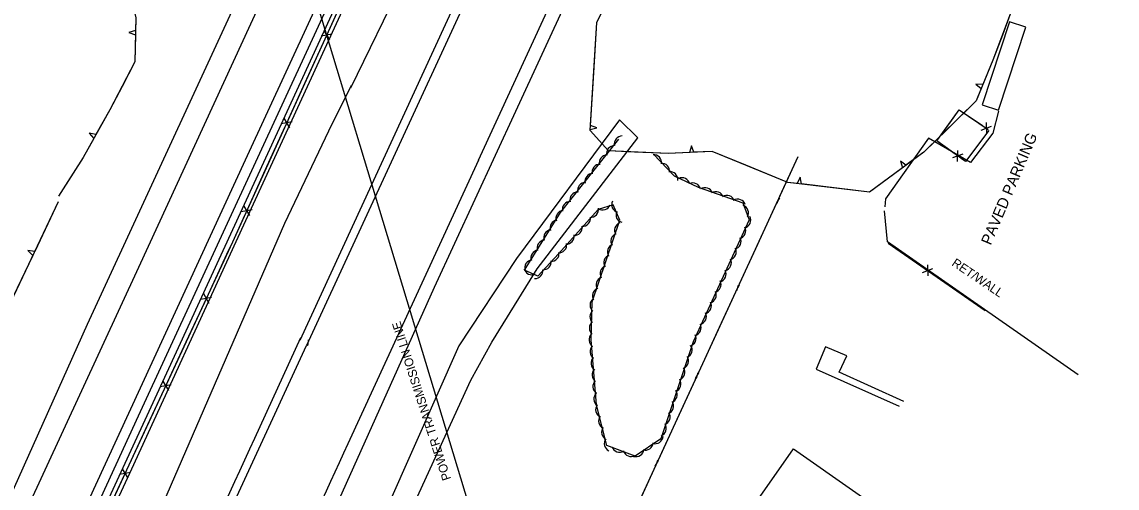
# Model space of a CAD drawing. Extents: x 978516 to 993312, y 1836504 to 1846212.
# Drawn here: x 982303.7 to 982802.5, y 1844142.7 to 1844355.2 of the extents above; entities that cross this region are included whole.
import ezdxf

# ---------------------------------------------------------------- set-up
doc = ezdxf.new("R2010")
doc.units = 0
for name, color, linetype in [('S_BUILDING', 7, 'Continuous'), ('S_EDGE_PAVEMENT', 7, 'Continuous'), ('S_FENCE', 7, 'Continuous'), ('S_IRON_PIN_ANNOT', 7, 'Continuous'), ('S_LANDSCAPING', 7, 'Continuous'), ('S_MISC_STRUCTURES', 7, 'Continuous'), ('S_PARKING', 7, 'Continuous'), ('S_PARKING_ANNOT', 7, 'Continuous'), ('S_SHOULDER', 7, 'Continuous'), ('S_SIDE_DRAIN', 7, 'Continuous'), ('S_SIDEWALK', 7, 'Continuous'), ('S_STREAM', 7, 'Continuous'), ('S_TREE', 7, 'Continuous'), ('S_UTILITY_POLE', 7, 'Continuous'), ('S_UTILITY_POLE_ANNOT', 7, 'Continuous')]:
    doc.layers.add(name, color=color, linetype=linetype)

msp = doc.modelspace()

# ---------------------------------------------------------------- linework, layer by layer
at = {"layer": 'S_BUILDING'}
msp.add_lwpolyline([(982748.58, 1844314.99), (982761, 1844352.77), (982753.47, 1844355.24), (982741.06, 1844317.46)], close=True, dxfattribs=at)
at = {"layer": 'S_EDGE_PAVEMENT'}
for points in [[(982779.67, 1844959.64), (982752.16, 1844900.15), (982714.25, 1844817.37), (982639.59, 1844655.47), (982545.18, 1844450.47), (982433.25, 1844207.72)], [(982511.65, 1844292.15), (982660.01, 1844614.55), (982735.58, 1844778.86), (982764.16, 1844843.59), (982802.52, 1844939.43)], [(982273.73, 1844064.89), (982288.19, 1844094.69), (982356.96, 1844243.34), (982421.2, 1844383.21)], [(982444.31, 1844376.55), (982405.39, 1844292.19), (982337.22, 1844143.95), (982258.29, 1843972.49), (982199.49, 1843845.15), (982150.27, 1843738.07), (982091.93, 1843611.5), (982046.43, 1843512.73)], [(982511.65, 1844292.15), (982452.19, 1844162.82)], [(982434.11, 1844208.11), (982434.24, 1844210.25)], [(982101.67, 1843487.19), (982177.28, 1843651.48), (982263.35, 1843838.34), (982337.41, 1843999.45), (982433.25, 1844207.72), (982434.11, 1844208.11)]]:
    msp.add_lwpolyline(points, dxfattribs=at)
msp.add_ellipse((985046.29, 1843010.45), major_axis=(-1542.42, -2755.9), ratio=0.898055, start_param=4.795233, end_param=4.843255, dxfattribs=at)
at = {"layer": 'S_FENCE'}
for p, q in [((982444.93, 1844349.65), (982440.03, 1844348.74)), ((982441.21, 1844351.35), (982443.75, 1844347.04)), ((982426.72, 1844309.61), (982421.82, 1844308.7)), ((982423.01, 1844311.31), (982425.54, 1844307)), ((982742.92, 1844309.32), (982742.99, 1844304.32)), ((982740.62, 1844305.93), (982745.29, 1844307.71)), ((982732.32, 1844294.9), (982727.59, 1844293.3)), ((982729.9, 1844291.6), (982730.01, 1844296.6)), ((982648.71, 1844275.09), (982647.19, 1844272.44)), ((982648.39, 1844275.04), (982647.51, 1844272.48)), ((982408.51, 1844269.57), (982403.61, 1844268.66)), ((982404.8, 1844271.27), (982407.33, 1844266.96)), ((982716.24, 1844244.4), (982716.27, 1844239.4)), ((982713.91, 1844241.03), (982718.6, 1844242.76)), ((982630.32, 1844235.15), (982628.8, 1844232.5)), ((982630, 1844235.1), (982629.12, 1844232.55)), ((982390.12, 1844229.6), (982385.21, 1844228.73)), ((982386.41, 1844231.33), (982388.91, 1844227)), ((982611.93, 1844195.22), (982610.42, 1844192.57)), ((982611.61, 1844195.17), (982610.74, 1844192.61)), ((982371.61, 1844189.7), (982366.7, 1844188.83)), ((982367.91, 1844191.43), (982370.4, 1844187.1)), ((982593.55, 1844155.28), (982592.03, 1844152.63)), ((982593.23, 1844155.24), (982592.35, 1844152.68)), ((982353.11, 1844149.8), (982348.19, 1844148.92)), ((982349.4, 1844151.52), (982351.9, 1844147.2))]:
    msp.add_line(p, q, dxfattribs=at)
for points in [[(982451.59, 1844369.22), (982399.56, 1844254.82), (982308.24, 1844057.91)], [(982451.59, 1844369.22), (982443.31, 1844351.02)], [(982441.65, 1844347.38), (982433.38, 1844329.18)], [(982433.38, 1844329.18), (982425.1, 1844310.98)], [(982744.06, 1844305.71), (982733.42, 1844291.56), (982720.48, 1844301.06), (982730.66, 1844315.16), (982743.86, 1844306.2)], [(982726.48, 1844309.36), (982730.66, 1844315.16), (982741.3, 1844307.94)], [(982728.34, 1844295.29), (982720.48, 1844301.06), (982726.48, 1844309.36)], [(982423.44, 1844307.34), (982415.17, 1844289.14)], [(982744.06, 1844305.71), (982733.42, 1844291.56), (982731.57, 1844292.92)], [(982415.17, 1844289.14), (982406.89, 1844270.94)], [(982657.14, 1844293.73), (982591.49, 1844151.14), (982536.58, 1844030.85)], [(982657.14, 1844293.73), (982648.78, 1844275.58)], [(982647.11, 1844271.95), (982638.75, 1844253.79)], [(982405.23, 1844267.3), (982399.56, 1844254.82), (982396.91, 1844249.12)], [(982698.19, 1844254.4), (982714.61, 1844243.03)], [(982698.19, 1844254.4), (982742.51, 1844223.71)], [(982396.91, 1844249.12), (982388.5, 1844230.98)], [(982638.75, 1844253.79), (982630.4, 1844235.64)], [(982717.9, 1844240.76), (982734.31, 1844229.39)], [(982628.73, 1844232.01), (982620.37, 1844213.86)], [(982734.31, 1844229.39), (982742.51, 1844223.71)], [(982386.82, 1844227.35), (982378.41, 1844209.21)], [(982378.41, 1844209.21), (982370, 1844191.08)], [(982620.37, 1844213.86), (982612.01, 1844195.71)], [(982610.34, 1844192.08), (982601.98, 1844173.93)], [(982368.31, 1844187.45), (982359.9, 1844169.31)], [(982359.9, 1844169.31), (982351.49, 1844151.17)], [(982601.98, 1844173.93), (982593.62, 1844155.77)], [(982591.95, 1844152.14), (982591.49, 1844151.14), (982583.68, 1844134.02)], [(982349.81, 1844147.55), (982341.4, 1844129.41)]]:
    msp.add_lwpolyline(points, dxfattribs=at)
at = {"layer": 'S_IRON_PIN_ANNOT'}
msp.add_lwpolyline([(982784.77, 1844194.32), (982697.96, 1844254.98), (982696.63, 1844269.13)], dxfattribs=at)
at = {"layer": 'S_MISC_STRUCTURES'}
msp.add_lwpolyline([(982459.15, 1844381.2), (982401.18, 1844255.02), (982353.6, 1844151.37), (982293.53, 1844021.64), (982233.45, 1843890.75), (982165.83, 1843744.12), (982112.95, 1843629.64), (982097.77, 1843596.62), (982091.45, 1843577), (982071.61, 1843534.32), (982068.38, 1843535.71), (982088.3, 1843578.12), (982096.35, 1843601.36), (982110.1, 1843631.18), (982228.09, 1843887.64), (982301.61, 1844047.37), (982364.37, 1844183.75), (982455.44, 1844381.81), (982456.19, 1844383.33)], dxfattribs=at)
at = {"layer": 'S_PARKING'}
for points in [[(982748.55, 1844314.55), (982745.93, 1844304.53), (982735.73, 1844291.12), (982716.57, 1844302.26), (982697.03, 1844274.58), (982696.68, 1844270.86)], [(982717.91, 1844043.16), (982620.49, 1844110.96), (982655.12, 1844160.56), (982713.37, 1844119.72)]]:
    msp.add_lwpolyline(points, dxfattribs=at)
at = {"layer": 'S_SHOULDER'}
for points in [[(982430.43, 1844210.12), (982524.82, 1844415.67), (982632.61, 1844650.66), (982722.13, 1844843.9), (982785.87, 1844983.8)], [(982805.21, 1844925.87), (982773.09, 1844849.82), (982754.04, 1844807.09), (982715.23, 1844720.47), (982650.33, 1844578.31), (982528.53, 1844314.43)], [(982281.93, 1844102.29), (982333.5, 1844217.4), (982416.97, 1844398.31)], [(982448.76, 1844375.28), (982356.61, 1844175.48), (982282.66, 1844014.59), (982233, 1843906.78), (982168.28, 1843765.4), (982106.74, 1843632.71), (982066.39, 1843545.71)], [(982528.53, 1844314.43), (982491.54, 1844234.12), (982441.42, 1844122.41), (982416.93, 1844065.19), (982403.54, 1844032.8)], [(982409.72, 1844165.47), (982430.67, 1844211.3), (982430.67, 1844211.3)]]:
    msp.add_lwpolyline(points, dxfattribs=at)
msp.add_ellipse((981492.34, 1844624.74), major_axis=(2158.84, 4724.25), ratio=0.197395, start_param=4.671769, end_param=4.705376, dxfattribs=at)
at = {"layer": 'S_SIDE_DRAIN'}
msp.add_lwpolyline([(982477.92, 1844125.85), (982508.24, 1844191.94), (982517.73, 1844209.18), (982538.43, 1844242.71), (982584.17, 1844302.32), (982575.94, 1844310.66), (982529, 1844247.39), (982502.74, 1844207.51), (982471.02, 1844135.94)], dxfattribs=at)
at = {"layer": 'S_SIDEWALK'}
msp.add_lwpolyline([(982705.47, 1844182.18), (982675.93, 1844195.5), (982679.5, 1844203.01), (982669.7, 1844207.13), (982665.52, 1844196.93), (982703.34, 1844180.05)], dxfattribs=at)
at = {"layer": 'S_STREAM'}
for points in [[(982514.14, 1844454.86), (982497.09, 1844420.18), (982477.21, 1844374.11), (982453.29, 1844325.07)], [(982296.86, 1843981.53), (982335.53, 1844064.99), (982369.8, 1844139.96), (982423.52, 1844263.5), (982443.56, 1844305.64), (982453.87, 1844326.44)]]:
    msp.add_lwpolyline(points, dxfattribs=at)
at = {"layer": 'S_TREE'}
for p, q in [((982355.46, 1844351.33), (982352.46, 1844350.46)), ((982352.46, 1844350.46), (982355.42, 1844349.37)), ((982741.38, 1844326.63), (982738.26, 1844326.91)), ((982738.26, 1844326.91), (982740.66, 1844324.87)), ((982337.39, 1844303.85), (982334.32, 1844304.5)), ((982334.32, 1844304.5), (982336.43, 1844302.14)), ((982562.51, 1844306.18), (982565.55, 1844306.88)), ((982565.55, 1844306.88), (982562.63, 1844308.06)), ((982608.61, 1844298.75), (982607.75, 1844295.72)), ((982609.71, 1844295.81), (982608.61, 1844298.75)), ((982706.35, 1844289.86), (982703.82, 1844291.72)), ((982703.82, 1844291.72), (982704.76, 1844288.7)), ((982658.24, 1844284.41), (982656.85, 1844281.57)), ((982658.79, 1844281.33), (982658.24, 1844284.41)), ((982309.53, 1844250.56), (982306.42, 1844250.99)), ((982306.42, 1844250.99), (982308.69, 1844248.78))]:
    msp.add_line(p, q, dxfattribs=at)
for points in [[(982804.27, 1844516.15), (982793.6, 1844477.25), (982784.63, 1844454.32), (982771.91, 1844403.14), (982762.4, 1844378), (982753.89, 1844358.77), (982745.95, 1844337.86), (982738.36, 1844319.23), (982714.53, 1844295.87), (982689.69, 1844277.63), (982652.61, 1844282.07), (982618.06, 1844296.21), (982598.05, 1844295.25), (982570.83, 1844296.38), (982562.48, 1844305.77), (982565.59, 1844354.93), (982623.79, 1844472.62), (982664.33, 1844560.24), (982697.9, 1844644.34), (982729.23, 1844720.38), (982762.23, 1844784.33), (982785.41, 1844824.53), (982793.95, 1844870.65), (982830.34, 1844936.28)], [(982299.87, 1844669.43), (982295.8, 1844661.17), (982287.04, 1844652.25), (982278.36, 1844646.68), (982281.7, 1844641.57), (982293.66, 1844618.48), (982300.13, 1844583.32), (982310.03, 1844572.3), (982316.34, 1844568.32), (982332.82, 1844540.93), (982346.52, 1844502.9), (982363.51, 1844467.01), (982368.2, 1844446.61), (982363.69, 1844428.13), (982348.64, 1844401.08), (982345.35, 1844388.33), (982351.79, 1844373.03), (982355.59, 1844357.06), (982355.13, 1844336.97), (982343.7, 1844315.15), (982331.57, 1844293.44), (982320.31, 1844275.73)], [(982350.68, 1844375.66), (982351.79, 1844373.03), (982355.59, 1844357.06), (982355.46, 1844351.33)], [(982759.7, 1844371.89), (982753.89, 1844358.77), (982750.27, 1844349.25)], [(982564.14, 1844331.98), (982565.59, 1844354.93), (982566.04, 1844355.84)], [(982355.42, 1844349.37), (982355.13, 1844336.97), (982349.29, 1844325.82)], [(982750.27, 1844349.25), (982745.95, 1844337.86), (982741.38, 1844326.63)], [(982562.63, 1844308.06), (982564.14, 1844331.98)], [(982349.29, 1844325.82), (982343.7, 1844315.15), (982337.39, 1844303.85)], [(982740.66, 1844324.87), (982738.36, 1844319.23), (982725.07, 1844306.2)], [(982582.79, 1844295.88), (982570.83, 1844296.38), (982562.48, 1844305.77), (982562.51, 1844306.18)], [(982725.07, 1844306.2), (982714.53, 1844295.87), (982706.35, 1844289.86)], [(982336.43, 1844302.14), (982331.57, 1844293.44), (982323.53, 1844280.78)], [(982591.41, 1844294.87), (982600.78, 1844285.12), (982611.78, 1844279.9), (982632.07, 1844272.72), (982634.97, 1844264.95), (982623.16, 1844239.08), (982609.38, 1844209.39), (982594.75, 1844165.1), (982583.02, 1844157.2), (982570.05, 1844162.08), (982565.42, 1844180.58), (982563, 1844210.27), (982563.49, 1844227.63), (982576.07, 1844264.88), (982573.02, 1844271.8), (982566.12, 1844269.67), (982548.13, 1844249.5), (982538.68, 1844239.28), (982532.62, 1844242.11), (982549.05, 1844268.3), (982575.51, 1844301.78)], [(982607.75, 1844295.72), (982598.05, 1844295.25), (982582.79, 1844295.88)], [(982633.45, 1844289.92), (982618.06, 1844296.21), (982609.71, 1844295.81)], [(982656.85, 1844281.57), (982652.61, 1844282.07), (982633.45, 1844289.92)], [(982704.76, 1844288.7), (982689.69, 1844277.63), (982683.49, 1844278.38)], [(982323.53, 1844280.78), (982320.31, 1844275.73)], [(982683.49, 1844278.38), (982658.79, 1844281.33)], [(982320.27, 1844273.13), (982294.35, 1844218.63), (982266.47, 1844155.73), (982254.26, 1844130.08)], [(982320.27, 1844273.13), (982309.53, 1844250.56)], [(982308.69, 1844248.78), (982297.95, 1844226.21)]]:
    msp.add_lwpolyline(points, dxfattribs=at)
for centre, major_axis, ratio, start_param, end_param in [((982573.63, 1844295.2), (-2.3, -2.83), 0.992567, 3.838882, 5.612082), ((982577.16, 1844299.61), (-2.3, -2.83), 0.992567, 3.838882, 5.612082), ((982570.26, 1844290.93), (-2.3, -2.83), 0.992567, 3.838882, 5.612082), ((982591.44, 1844290.99), (-2.64, -2.52), 0.996815, 2.258068, 4.031269), ((982567, 1844286.75), (-2.3, -2.83), 0.992567, 3.838882, 5.612082), ((982595.07, 1844287.11), (-2.64, -2.52), 0.996815, 2.258068, 4.031269), ((982563.78, 1844282.56), (-2.3, -2.83), 0.992567, 3.838882, 5.612082), ((982598.77, 1844283.36), (-2.64, -2.52), 0.996815, 2.258068, 4.031269), ((982604.34, 1844280.52), (-2.14, 2.95), 0.998758, 4.324931, 6.098131), ((982560.42, 1844278.42), (-2.3, -2.83), 0.992567, 3.838882, 5.612082), ((982609.25, 1844278.19), (-2.14, 2.95), 0.998758, 4.324931, 6.098131), ((982614.75, 1844276.03), (-2.59, 2.56), 0.998121, 4.266151, 6.039352), ((982556.89, 1844274.01), (-2.3, -2.83), 0.992567, 3.838882, 5.612082), ((982619.76, 1844274.18), (-2.59, 2.56), 0.998121, 4.266151, 6.039352), ((982624.76, 1844272.49), (-2.59, 2.56), 0.998121, 4.266151, 6.039352), ((982629.77, 1844270.75), (-2.59, 2.56), 0.998121, 4.266151, 6.039352), ((982550.58, 1844265.75), (-3.62, -0.4), 0.981117, 4.73599, 6.509191), ((982553.51, 1844269.74), (-2.3, -2.83), 0.992567, 3.838882, 5.612082), ((982562.67, 1844269.72), (2.59, 2.56), 0.992445, 3.889224, 5.662425), ((982568.26, 1844273.1), (3.05, 1.99), 0.993469, 3.544887, 5.318088), ((982575.93, 1844271.98), (-3.11, -1.9), 0.944949, 5.270716, 7.043916), ((982630.99, 1844268.13), (-0.38, 3.62), 0.99871, 4.077832, 5.851033), ((982547.86, 1844261.29), (-3.62, -0.4), 0.981117, 4.73599, 6.509191), ((982559.05, 1844265.66), (2.59, 2.56), 0.992445, 3.889224, 5.662425), ((982577.89, 1844267.33), (-3.11, -1.9), 0.944949, 5.270716, 7.043916), ((982632.04, 1844264.89), (1.66, 3.25), 0.99343, 3.869486, 5.642687), ((982545, 1844256.87), (-3.62, -0.4), 0.981117, 4.73599, 6.509191), ((982555.26, 1844261.46), (2.59, 2.56), 0.992445, 3.889224, 5.662425), ((982577.29, 1844260.33), (-3.61, -0.47), 0.967867, 4.953782, 6.726983), ((982629.76, 1844260.07), (1.66, 3.25), 0.99343, 3.869486, 5.642687), ((982542, 1844252.16), (-3.62, -0.4), 0.981117, 4.73599, 6.509191), ((982548.2, 1844253.54), (2.59, 2.56), 0.992445, 3.889224, 5.662425), ((982551.66, 1844257.53), (2.59, 2.56), 0.992445, 3.889224, 5.662425), ((982575.59, 1844255.31), (-3.61, -0.47), 0.967867, 4.953782, 6.726983), ((982627.63, 1844255.23), (1.66, 3.25), 0.99343, 3.869486, 5.642687), ((982539.14, 1844247.6), (-3.62, -0.4), 0.981117, 4.73599, 6.509191), ((982544.69, 1844249.61), (3.5, -1), 0.960132, 4.943705, 6.716905), ((982573.97, 1844250.41), (-3.61, -0.47), 0.967867, 4.953782, 6.726983), ((982625.46, 1844250.39), (1.66, 3.25), 0.99343, 3.869486, 5.642687), ((982536.38, 1844243.15), (-3.62, -0.4), 0.981117, 4.73599, 6.509191), ((982541.11, 1844245.75), (3.5, -1), 0.960132, 4.943705, 6.716905), ((982572.4, 1844245.51), (-3.61, -0.47), 0.967867, 4.953782, 6.726983), ((982623.2, 1844245.44), (1.66, 3.25), 0.99343, 3.869486, 5.642687), ((982535.97, 1844243.56), (3.05, 1.99), 0.996507, 2.809911, 4.583112), ((982537.37, 1844241.76), (3.5, -1), 0.960132, 4.943705, 6.716905), ((982570.67, 1844240.61), (-3.61, -0.47), 0.967867, 4.953782, 6.726983), ((982620.82, 1844240.32), (1.66, 3.25), 0.99343, 3.869486, 5.642687), ((982568.88, 1844235.41), (-3.61, -0.47), 0.967867, 4.953782, 6.726983), ((982618.52, 1844235.52), (1.89, 3.12), 0.993335, 3.935751, 5.708952), ((982566.1, 1844226.12), (-3.04, -2.01), 0.98828, 4.789539, 6.56274), ((982567.18, 1844230.39), (-3.61, -0.47), 0.967867, 4.953782, 6.726983), ((982616.36, 1844230.7), (1.89, 3.12), 0.993335, 3.935751, 5.708952), ((982614.16, 1844225.87), (1.89, 3.12), 0.993335, 3.935751, 5.708952), ((982566.03, 1844220.88), (-3.04, -2.01), 0.98828, 4.789539, 6.56274), ((982611.86, 1844220.94), (1.89, 3.12), 0.993335, 3.935751, 5.708952), ((982565.8, 1844215.59), (-3.04, -2.01), 0.98828, 4.789539, 6.56274), ((982609.46, 1844215.83), (1.89, 3.12), 0.993335, 3.935751, 5.708952), ((982565.63, 1844210.25), (0.15, -3.64), 0.996942, 3.865623, 5.638823), ((982607.15, 1844211.02), (1.89, 3.12), 0.993335, 3.935751, 5.708952), ((982566.07, 1844204.83), (0.15, -3.64), 0.996942, 3.865623, 5.638823), ((982605.38, 1844205.71), (2.76, 2.37), 0.991922, 4.371553, 6.144754), ((982566.54, 1844199.54), (0.15, -3.64), 0.996942, 3.865623, 5.638823), ((982603.75, 1844200.68), (2.76, 2.37), 0.991922, 4.371553, 6.144754), ((982567.04, 1844194.28), (0.15, -3.64), 0.996942, 3.865623, 5.638823), ((982602.05, 1844195.52), (2.76, 2.37), 0.991922, 4.371553, 6.144754), ((982567.4, 1844188.96), (0.15, -3.64), 0.996942, 3.865623, 5.638823), ((982600.25, 1844190.18), (2.76, 2.37), 0.991922, 4.371553, 6.144754), ((982567.83, 1844183.33), (0.15, -3.64), 0.996942, 3.865623, 5.638823), ((982598.51, 1844185.15), (2.76, 2.37), 0.991922, 4.371553, 6.144754), ((982568.67, 1844178.4), (3.04, -2.01), 0.996453, 3.082614, 4.855815), ((982596.92, 1844180.12), (2.76, 2.37), 0.991922, 4.371553, 6.144754), ((982569.99, 1844173.27), (3.04, -2.01), 0.996453, 3.082614, 4.855815), ((982595.3, 1844175.09), (2.76, 2.37), 0.991922, 4.371553, 6.144754), ((982571.34, 1844168.17), (3.04, -2.01), 0.996453, 3.082614, 4.855815), ((982593.59, 1844169.93), (2.76, 2.37), 0.991922, 4.371553, 6.144754), ((982572.56, 1844162.99), (3.04, -2.01), 0.996453, 3.082614, 4.855815), ((982592.09, 1844166.5), (3.62, -0.43), 0.986984, 4.542816, 6.316016), ((982575.96, 1844162.66), (0.76, -3.56), 0.995021, 4.828306, 6.601507), ((982581.04, 1844160.75), (0.76, -3.56), 0.995021, 4.828306, 6.601507), ((982583.34, 1844160.6), (3.62, -0.43), 0.986984, 4.542816, 6.316016), ((982587.65, 1844163.59), (3.62, -0.43), 0.986984, 4.542816, 6.316016)]:
    msp.add_ellipse(centre, major_axis=major_axis, ratio=ratio, start_param=start_param, end_param=end_param, dxfattribs=at)
at = {"layer": 'S_UTILITY_POLE'}
msp.add_lwpolyline([(982551.45, 1843989.01), (982341.16, 1844684.77), (982446.38, 1845348.34)], dxfattribs=at)

# ---------------------------------------------------------------- texts
at = {"layer": 'S_LANDSCAPING'}
msp.add_text('RET/WALL', height=4, rotation=325.925, dxfattribs=at).set_placement((982726.89, 1844244.42))
at = {"layer": 'S_PARKING_ANNOT'}
msp.add_text('PAVED PARKING', height=5.0005, rotation=66.9905, dxfattribs=at).set_placement((982744.98, 1844253.11))
at = {"layer": 'S_UTILITY_POLE_ANNOT'}
msp.add_text('POWER TRANSMISSION LINE', height=4.0004, rotation=107.8513, dxfattribs=at).set_placement((982499.21, 1844146.9))

doc.saveas('drawing.dxf')
